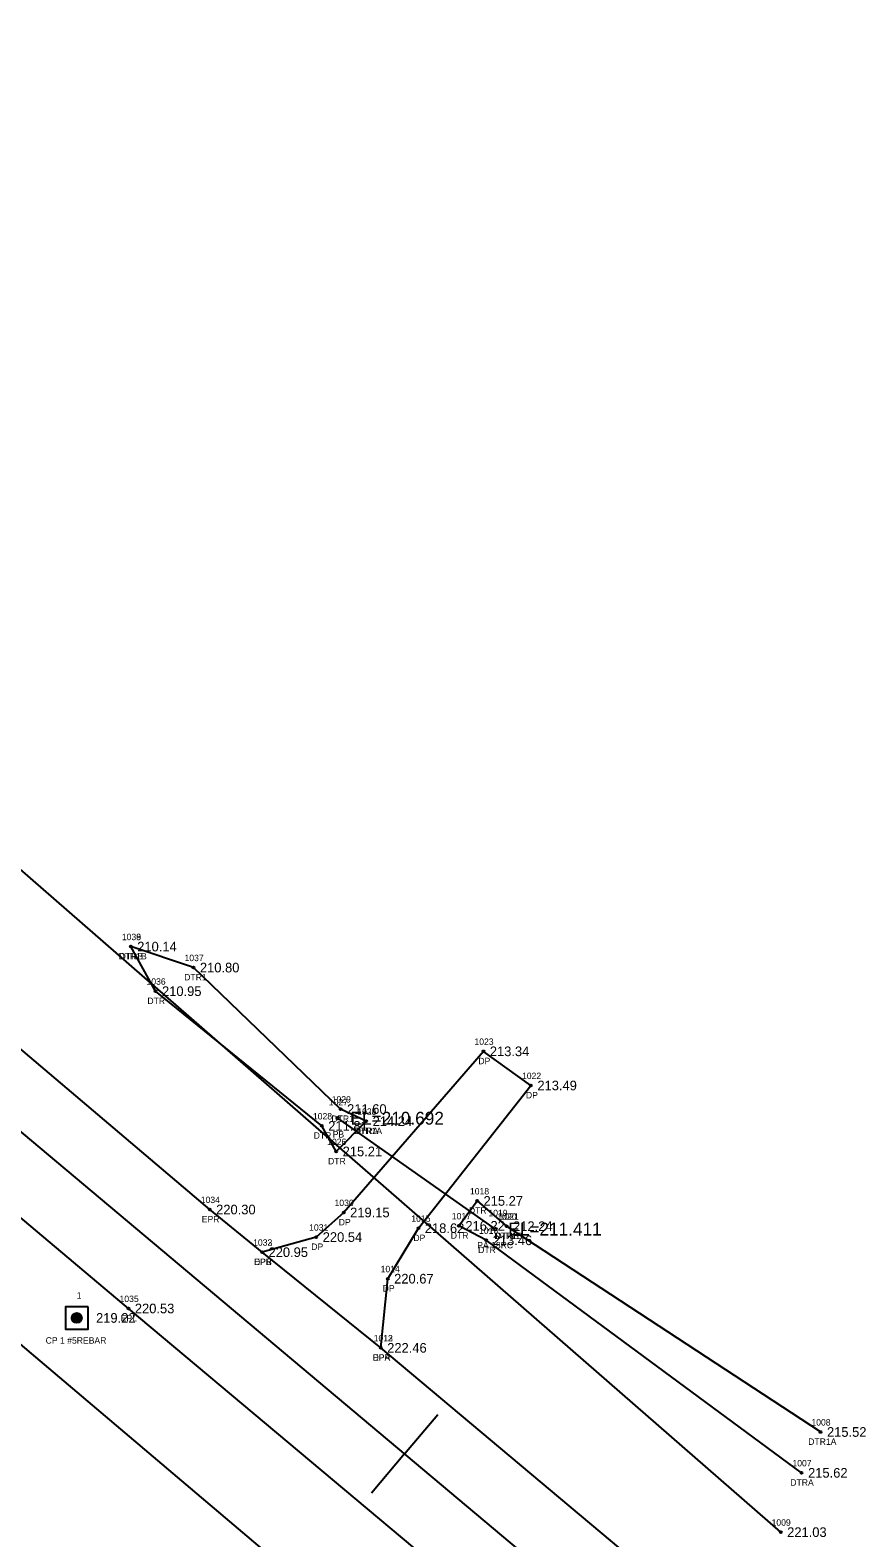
# Model space of a CAD drawing. Extents: x 2259948 to 2261336, y 1064647 to 1065986.
# Drawn here: x 2261017.7 to 2261147.5, y 1064842.1 to 1065076.4 of the extents above; entities that cross this region are included whole.
import ezdxf

# ---------------------------------------------------------------- set-up
doc = ezdxf.new("R2010")
doc.units = 0
for name, color, linetype in [('RD_EX_DR_Pipe', 7, 'Continuous'), ('RD_EX_DR_Pipe_txCode', 7, 'Continuous'), ('RD_EX_Driveway', 7, 'Continuous'), ('RD_EX_Driveway_txCode', 7, 'Continuous'), ('RD_EX_H2O', 7, 'Continuous'), ('RD_EX_H2O_txCode', 7, 'Continuous'), ('RD_EX_Road', 7, 'Continuous'), ('RD_EX_Road_txCode', 7, 'Continuous'), ('RD_EX_TX_Driveway_ELEV', 7, 'Continuous'), ('RD_EX_TX_H2O_ELEV', 7, 'Continuous'), ('RD_EX_TX_Road_ELEV', 7, 'Continuous'), ('RD_EX_TX_VEG_ELEV', 7, 'Continuous'), ('RD_EX_VEG', 7, 'Continuous'), ('RD_EX_VEG_txCode', 7, 'Continuous'), ('RD_HC_Cl', 7, 'Continuous'), ('RD_HC_Data_Tic', 7, 'Continuous'), ('RD_HC_Survey', 7, 'Continuous'), ('RD_HC_Survey_ELEV', 7, 'Continuous'), ('RD_HC_Survey_txCode', 7, 'Continuous'), ('RD_SMD_Locator', 7, 'Continuous'), ('RD_TX_Pipe_ElevEX', 7, 'Continuous')]:
    doc.layers.add(name, color=color, linetype=linetype)

msp = doc.modelspace()

# ---------------------------------------------------------------- linework, layer by layer
at = {"layer": 'RD_EX_DR_Pipe'}
msp.add_line((2261089.99, 1064890.06), (2261065.47, 1064907.29), dxfattribs=at)
at = {"layer": 'RD_EX_Driveway'}
msp.add_lwpolyline([(2261072.16, 1064871.6), (2261073.24, 1064882.35), (2261078.01, 1064890.2), (2261095.5, 1064912.38), (2261088.11, 1064917.69), (2261066.4, 1064892.64), (2261062.14, 1064888.82), (2261053.72, 1064886.47)], dxfattribs=at)
at = {"layer": 'RD_EX_H2O'}
msp.add_line((2261140.5, 1064858.52), (2261091.72, 1064890.51), dxfattribs=at)
for points in [[(2261069.9, 1064906.82), (2261065.24, 1064902.13), (2261063, 1064906.1), (2261037.17, 1064927.04), (2261033.32, 1064933.97)], [(2261069.9, 1064906.82), (2261065.93, 1064908.72), (2261043.06, 1064930.71), (2261033.32, 1064933.97)], [(2261137.56, 1064852.17), (2261088.56, 1064888.32), (2261084.31, 1064890.57), (2261087.13, 1064894.44), (2261091.72, 1064890.51)]]:
    msp.add_lwpolyline(points, dxfattribs=at)
at = {"layer": 'RD_EX_Road'}
for points in [[(2261124.91, 1064827.37), (2261072.16, 1064871.6), (2261053.72, 1064886.47), (2261045.58, 1064893.1), (2260972.89, 1064954.76), (2260940.74, 1064982.39), (2260933.33, 1064988.76), (2260898.06, 1065017.6), (2260832.89, 1065075.07)], [(2261112.68, 1064810.86), (2261032.95, 1064877.72), (2260956.01, 1064942.53), (2260884.53, 1065002.6), (2260818.6, 1065058.26)]]:
    msp.add_lwpolyline(points, dxfattribs=at)
at = {"layer": 'RD_EX_VEG'}
for points in [[(2261134.31, 1064842.95), (2260842.2, 1065097.67), (2260806.91, 1065126.77), (2260758.4, 1065156.57), (2260401.57, 1065481.47), (2260414.95, 1065532.7)], [(2261105.29, 1064796.67), (2260883, 1064984.96), (2260766.14, 1065062.68), (2260367.33, 1065416.28), (2260257.33, 1065527.76)]]:
    msp.add_lwpolyline(points, dxfattribs=at)
at = {"layer": 'RD_HC_Cl'}
msp.add_line((2261118.79, 1064819.11), (2260589.55, 1065263.13), dxfattribs=at)
at = {"layer": 'RD_HC_Data_Tic'}
for q in [(2261081.01, 1064861.25), (2261070.73, 1064848.99)]:
    msp.add_line((2261075.87, 1064855.12), q, dxfattribs=at)
at = {"layer": 'RD_HC_Survey'}
for p, q in [((2261024.17, 1064876.07), (2261024.17, 1064876.43)), ((2261024.2, 1064875.99), (2261024.2, 1064876.51)), ((2261024.22, 1064875.92), (2261024.22, 1064876.57)), ((2261024.25, 1064875.88), (2261024.25, 1064876.62)), ((2261024.27, 1064875.83), (2261024.27, 1064876.66)), ((2261024.3, 1064875.8), (2261024.3, 1064876.7)), ((2261024.32, 1064875.76), (2261024.32, 1064876.73)), ((2261024.35, 1064875.74), (2261024.35, 1064876.76)), ((2261024.37, 1064875.71), (2261024.37, 1064876.78)), ((2261024.4, 1064875.68), (2261024.4, 1064876.81)), ((2261024.42, 1064875.66), (2261024.42, 1064876.83)), ((2261024.45, 1064875.64), (2261024.45, 1064876.85)), ((2261024.47, 1064875.62), (2261024.47, 1064876.87)), ((2261024.5, 1064875.61), (2261024.5, 1064876.89)), ((2261024.52, 1064875.59), (2261024.52, 1064876.9)), ((2261024.55, 1064875.58), (2261024.55, 1064876.92)), ((2261024.57, 1064875.56), (2261024.57, 1064876.93)), ((2261024.6, 1064875.55), (2261024.6, 1064876.94)), ((2261024.62, 1064875.54), (2261024.62, 1064876.95)), ((2261024.64, 1064875.53), (2261024.64, 1064876.96)), ((2261024.67, 1064875.52), (2261024.67, 1064876.97)), ((2261024.69, 1064875.51), (2261024.69, 1064876.98)), ((2261024.72, 1064875.5), (2261024.72, 1064876.99)), ((2261024.74, 1064875.5), (2261024.74, 1064877)), ((2261024.77, 1064875.49), (2261024.77, 1064877)), ((2261024.79, 1064875.49), (2261024.79, 1064877.01)), ((2261024.82, 1064875.48), (2261024.82, 1064877.01)), ((2261024.84, 1064875.48), (2261024.84, 1064877.01)), ((2261024.87, 1064875.48), (2261024.87, 1064877.01)), ((2261024.89, 1064875.48), (2261024.89, 1064877.02)), ((2261024.92, 1064875.48), (2261024.92, 1064877.02)), ((2261024.94, 1064875.48), (2261024.94, 1064877.02)), ((2261024.97, 1064875.48), (2261024.97, 1064877.02)), ((2261024.99, 1064875.48), (2261024.99, 1064877.01)), ((2261025.02, 1064875.48), (2261025.02, 1064877.01)), ((2261025.04, 1064875.49), (2261025.04, 1064877.01)), ((2261025.07, 1064875.49), (2261025.07, 1064877)), ((2261025.09, 1064875.5), (2261025.09, 1064877)), ((2261025.12, 1064875.5), (2261025.12, 1064876.99)), ((2261025.14, 1064875.51), (2261025.14, 1064876.99)), ((2261025.16, 1064875.52), (2261025.16, 1064876.98)), ((2261025.19, 1064875.52), (2261025.19, 1064876.97)), ((2261025.21, 1064875.53), (2261025.21, 1064876.96)), ((2261025.24, 1064875.55), (2261025.24, 1064876.95)), ((2261025.26, 1064875.56), (2261025.26, 1064876.94)), ((2261025.29, 1064875.57), (2261025.29, 1064876.92)), ((2261025.31, 1064875.58), (2261025.31, 1064876.91)), ((2261025.34, 1064875.6), (2261025.34, 1064876.89)), ((2261025.36, 1064875.62), (2261025.36, 1064876.88)), ((2261025.39, 1064875.63), (2261025.39, 1064876.86)), ((2261025.41, 1064875.65), (2261025.41, 1064876.84)), ((2261025.44, 1064875.67), (2261025.44, 1064876.82)), ((2261025.46, 1064875.7), (2261025.46, 1064876.8)), ((2261025.49, 1064875.72), (2261025.49, 1064876.77)), ((2261025.51, 1064875.75), (2261025.51, 1064876.74)), ((2261025.54, 1064875.78), (2261025.54, 1064876.71)), ((2261025.56, 1064875.82), (2261025.56, 1064876.68)), ((2261025.59, 1064875.86), (2261025.59, 1064876.64)), ((2261025.61, 1064875.9), (2261025.61, 1064876.59)), ((2261025.63, 1064875.95), (2261025.63, 1064876.54)), ((2261025.66, 1064876.02), (2261025.66, 1064876.47)), ((2261025.68, 1064876.14), (2261025.68, 1064876.36))]:
    msp.add_line(p, q, dxfattribs=at)
msp.add_lwpolyline([(2261026.67, 1064878), (2261023.17, 1064878), (2261023.17, 1064874.5), (2261026.67, 1064874.5)], close=True, dxfattribs=at)
msp.add_circle((2261024.92, 1064876.25), 0.769, dxfattribs=at)
at = {"layer": 'RD_SMD_Locator'}
for centre, radius in [((2261033.32, 1064933.97), 0.15), ((2261033.32, 1064933.97), 0.15), ((2261043.06, 1064930.71), 0.15), ((2261037.17, 1064927.04), 0.15), ((2261088.11, 1064917.69), 0.15), ((2261095.5, 1064912.38), 0.15), ((2261065.93, 1064908.72), 0.15), ((2261063, 1064906.1), 0.15), ((2261065.47, 1064907.29), 0.2), ((2261069.9, 1064906.82), 0.15), ((2261069.9, 1064906.82), 0.15), ((2261065.24, 1064902.13), 0.15), ((2261087.13, 1064894.44), 0.15), ((2261045.58, 1064893.1), 0.15), ((2261066.4, 1064892.64), 0.15), ((2261062.14, 1064888.82), 0.15), ((2261078.01, 1064890.2), 0.15), ((2261084.31, 1064890.57), 0.15), ((2261089.99, 1064890.06), 0.2), ((2261091.72, 1064890.51), 0.15), ((2261091.72, 1064890.51), 0.15), ((2261053.72, 1064886.47), 0.15), ((2261053.72, 1064886.47), 0.15), ((2261088.56, 1064888.32), 0.15), ((2261073.24, 1064882.35), 0.15), ((2261032.95, 1064877.72), 0.15), ((2261024.92, 1064876.25), 0.15), ((2261072.16, 1064871.6), 0.15), ((2261072.16, 1064871.6), 0.15), ((2261140.5, 1064858.52), 0.15), ((2261137.56, 1064852.17), 0.15), ((2261134.31, 1064842.95), 0.15)]:
    msp.add_circle(centre, radius, dxfattribs=at)

# ---------------------------------------------------------------- texts
at = {"layer": 'RD_EX_DR_Pipe_txCode'}
for s, p in [('1027', (2261064.08, 1064909.29)), ('PB', (2261064.69, 1064904.29)), ('1019', (2261088.89, 1064892.06)), ('PA 18RC', (2261087.15, 1064887.06))]:
    msp.add_text(s, height=1, dxfattribs=at).set_placement(p)
at = {"layer": 'RD_EX_Driveway_txCode'}
for s, p in [('1023', (2261086.72, 1064918.69)), ('DP', (2261087.33, 1064915.69)), ('1022', (2261094.11, 1064913.38)), ('DP', (2261094.72, 1064910.38)), ('1030', (2261064.98, 1064893.64)), ('DP', (2261065.63, 1064890.64)), ('1015', (2261076.91, 1064891.2)), ('1031', (2261061.03, 1064889.82)), ('DP', (2261077.23, 1064888.2)), ('1032', (2261052.33, 1064887.47)), ('DP', (2261061.36, 1064886.82)), ('DPB', (2261052.47, 1064884.47)), ('1014', (2261072.14, 1064883.35)), ('DP', (2261072.46, 1064880.35)), ('1013', (2261071.06, 1064872.6)), ('DPA', (2261070.89, 1064869.6))]:
    msp.add_text(s, height=1, dxfattribs=at).set_placement(p)
at = {"layer": 'RD_EX_H2O_txCode'}
for s, p in [('1038', (2261031.93, 1064934.97)), ('1039', (2261031.93, 1064934.97)), ('DTR1B', (2261031.41, 1064931.97)), ('DTRB', (2261031.58, 1064931.97)), ('1037', (2261041.67, 1064931.71)), ('1036', (2261035.76, 1064928.04)), ('DTR1', (2261041.62, 1064928.71)), ('DTR', (2261035.9, 1064925.04)), ('1029', (2261064.54, 1064909.72)), ('1028', (2261061.62, 1064907.1)), ('DTR1', (2261064.5, 1064906.72)), ('1024', (2261068.52, 1064907.82)), ('1025', (2261068.52, 1064907.82)), ('DTR1A', (2261067.98, 1064904.82)), ('DTRA', (2261068.14, 1064904.82)), ('DTR', (2261061.74, 1064904.1)), ('1026', (2261063.83, 1064903.13)), ('DTR', (2261063.97, 1064900.13)), ('1018', (2261086.02, 1064895.44)), ('1017', (2261083.2, 1064891.57)), ('DTR', (2261085.86, 1064892.44)), ('1020', (2261090.3, 1064891.51)), ('1021', (2261090.62, 1064891.51)), ('DTR', (2261083.04, 1064888.57)), ('1016', (2261087.43, 1064889.32)), ('DTR1B', (2261089.82, 1064888.51)), ('DTRB', (2261089.98, 1064888.51)), ('DTR', (2261087.29, 1064886.32)), ('1008', (2261139.08, 1064859.52)), ('DTR1A', (2261138.58, 1064856.52)), ('1007', (2261136.13, 1064853.17)), ('DTRA', (2261135.8, 1064850.17))]:
    msp.add_text(s, height=1, dxfattribs=at).set_placement(p)
at = {"layer": 'RD_EX_Road_txCode'}
for s, p in [('1034', (2261044.19, 1064894.1)), ('EPR', (2261044.35, 1064891.1)), ('1033', (2261052.33, 1064887.47)), ('EPR', (2261052.49, 1064884.47)), ('1035', (2261031.57, 1064878.72)), ('EPL', (2261031.75, 1064875.72)), ('1012', (2261071.06, 1064872.6)), ('EPR', (2261070.93, 1064869.6))]:
    msp.add_text(s, height=1, dxfattribs=at).set_placement(p)
at = {"layer": 'RD_EX_TX_Driveway_ELEV'}
for s, p in [('213.34', (2261089.11, 1064916.94)), ('213.49', (2261096.5, 1064911.63)), ('219.15', (2261067.4, 1064891.89)), ('220.54', (2261063.14, 1064888.07)), ('218.62', (2261079.01, 1064889.45)), ('220.95', (2261054.72, 1064885.72)), ('220.67', (2261074.24, 1064881.6)), ('222.46', (2261073.16, 1064870.85))]:
    msp.add_text(s, height=1.5, dxfattribs=at).set_placement(p)
at = {"layer": 'RD_EX_TX_H2O_ELEV'}
for s, p in [('210.14', (2261034.32, 1064933.22)), ('210.14', (2261034.32, 1064933.22)), ('210.80', (2261044.06, 1064929.96)), ('210.95', (2261038.17, 1064926.29)), ('211.60', (2261066.93, 1064907.97)), ('211.81', (2261064, 1064905.35)), ('214.24', (2261070.9, 1064906.07)), ('214.24', (2261070.9, 1064906.07)), ('215.21', (2261066.24, 1064901.38)), ('215.27', (2261088.13, 1064893.69)), ('216.22', (2261085.31, 1064889.82)), ('213.46', (2261089.56, 1064887.57)), ('212.24', (2261092.72, 1064889.76)), ('212.24', (2261092.72, 1064889.76)), ('215.52', (2261141.5, 1064857.77)), ('215.62', (2261138.56, 1064851.42))]:
    msp.add_text(s, height=1.5, dxfattribs=at).set_placement(p)
at = {"layer": 'RD_EX_TX_Road_ELEV'}
for s, p in [('220.30', (2261046.58, 1064892.35)), ('220.95', (2261054.72, 1064885.72)), ('220.53', (2261033.95, 1064876.97)), ('222.46', (2261073.16, 1064870.85))]:
    msp.add_text(s, height=1.5, dxfattribs=at).set_placement(p)
at = {"layer": 'RD_EX_TX_VEG_ELEV'}
msp.add_text('221.03', height=1.5, dxfattribs=at).set_placement((2261135.31, 1064842.2))
at = {"layer": 'RD_EX_VEG_txCode'}
msp.add_text('1009', height=1, dxfattribs=at).set_placement((2261132.89, 1064843.95))
at = {"layer": 'RD_HC_Survey_ELEV'}
msp.add_text('219.22', height=1.5, dxfattribs=at).set_placement((2261027.92, 1064875.5))
at = {"layer": 'RD_HC_Survey_txCode'}
for s, p in [('1', (2261024.92, 1064879.25)), ('CP 1 #5REBAR', (2261020.09, 1064872.25))]:
    msp.add_text(s, height=1, dxfattribs=at).set_placement(p)
at = {"layer": 'RD_TX_Pipe_ElevEX'}
for s, p in [('EL=210.692', (2261067.47, 1064906.29)), ('EL=211.411', (2261091.99, 1064889.06))]:
    msp.add_text(s, height=2, dxfattribs=at).set_placement(p)

doc.saveas('drawing.dxf')
